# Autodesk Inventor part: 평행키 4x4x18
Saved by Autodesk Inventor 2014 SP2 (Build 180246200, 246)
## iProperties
Created: 2024-04
Part Number: 평행키 4x4x18
Material: Generic
Document SubType Name: Modeling
Designer: Administrator
Density: 1 g/cm^3
Appearance: Default
Author: Administrator
Author: jhkim
Description: 키 및 해당 키홈
Creation Date: 2024-04-08
Sending System: Autodesk Inventor 2025
Preprocessor: ST-DEVELOPER v20
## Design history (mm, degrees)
node "평행키 4x4x181"
body "Solid1"
node "기준1"
